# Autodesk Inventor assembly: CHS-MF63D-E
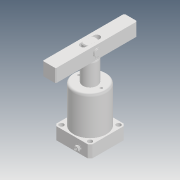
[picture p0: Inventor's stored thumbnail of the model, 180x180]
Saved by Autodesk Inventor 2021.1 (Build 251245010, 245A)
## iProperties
Created: 2019-05
Part Number: CHS-MF63D-E
Description: STEP AP203
Document SubType Name: Assembly
Designer: user
Title: chs-mf63d-e_asm.STEP
Revision Number: ÈÎºÎ
Sending System: SolidWorks 2017
Preprocessor: SwSTEP 2.0
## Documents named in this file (10)
- D:\Vault_2016\Projekty\Clamptek\Hydraulic\CHS\CHS-63\Inventor\CHS-MF63D-E\CHS-MF63D-E.iam
- D:\Vault_2016\Projekty\Clamptek\Hydraulic\CHS\CHS-63\Inventor\CHS-MF63D-E\CHS-MF63-03-E.ipt
- D:\Vault_2016\Projekty\Clamptek\Hydraulic\CHS\CHS-63\Inventor\CHS-MF63D-E\CHS-63D-01_3.ipt
- D:\Vault_2016\Projekty\Clamptek\Hydraulic\CHS\CHS-63\Inventor\CHS-MF63D-E\CHS-TXF-01_1.ipt
- D:\Vault_2016\Projekty\Clamptek\Hydraulic\CHS\CHS-63\Inventor\CHS-MF63D-E\CHS-MF40-TXF-03_1.ipt
- D:\Vault_2016\Projekty\Clamptek\Hydraulic\CHS\CHS-63\Inventor\CHS-MF63D-E\CHS-MF40-TXF-02_1.ipt
- D:\Vault_2016\Projekty\Clamptek\Hydraulic\CHS\CHS-63\Inventor\CHS-MF63D-E\M6_1.ipt
- D:\Vault_2016\Projekty\Clamptek\Hydraulic\CHS\CHS-63\Inventor\CHS-MF63D-E\¶ÌÏú.ipt
- D:\Vault_2016\Projekty\Clamptek\Hydraulic\CHS\CHS-63\Inventor\CHS-MF63D-E\¿¨»É.ipt
- D:\Vault_2016\Projekty\Clamptek\Hydraulic\CHS\CHS-63\Inventor\CHS-MF63D-E\CHS-63D-E»îÈû¸Ë_1.ipt
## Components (10 placed, 10 different names)
1. CHS-MF63-03-E_1
2. CHS-63D-01_3_2
3. CHS-TXF-01_1_3
4. CHS-MF40-TXF-03_1_4
5. CHS-MF40-TXF-02_1_5
6. M6_1_6
7. ¶ÌÏú_7
8. ¿¨»É_8
9. ¿¨»É_9
10. CHS-63D-E»îÈû¸Ë_1_10
